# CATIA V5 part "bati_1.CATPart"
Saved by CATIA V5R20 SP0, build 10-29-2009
Part number: sqlt_bati_1
Publications: "Plan.1", "Point.1", "Point.2", "Droite.1", "Droite.2", "Point.3", "Point.4", "Point.5", "Point.6", "Point.7", "Point.8", "Point.9", "Droite.3", "Point.10", "Point.11", "Point.12", "Point.13", "Point.14", "Point.15", "Point.16", "Point.17", "Plan.2", "Plan.3", "Plan.4", "Point.18", "Plan.5", "écartement_pivot_bati", "largueur_rail_coulisseau", "longueur_rail_coulisseau", "Plan.6", "Droite.4"
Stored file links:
  D:\ecole\thinkmotion\IAO\bati_1.CATPart
  D:\ecole\thinkmotion\IAO\sqlt mecanisme coulisseau.CATProduct
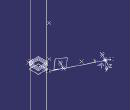
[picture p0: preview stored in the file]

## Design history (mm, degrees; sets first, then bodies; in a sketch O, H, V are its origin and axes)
Parameters
  `écartement_pivot_bati` = 100 mm {= `External.écartement_pivots`}
  largueur_rail_coulisseau = 50 mm {= External.largueur_rail_coulisseau}
  longueur_rail_coulisseau = 200 mm {= External.longueur_rail_coulisseau}
External parameters (linked from other documents)
  External.rayon_pivot_bati = 10 mm
  `External.épaisseur_piece` = 20 mm
  `External.écartement_pivots` = 100 mm
  External.largueur_rail_coulisseau = 50 mm
  External.longueur_rail_coulisseau = 200 mm
AxisSystem1: origin (-243.1672, 186.5836, 0), X (0.8944, -0.4472, 0), Y (0, 0, -1), Z (0.4472, 0.8944, 0)
Set1 "sqlt_bati"
  Plane1: type Offset, RefPlane xy-plane, Offset 0
  Point1: (0, 50 {= `écartement_pivot_bati` /2}, 0)
  Point2: (0, -50 {= -`écartement_pivot_bati` /2}, 0)
  Line1: type PtDir, RefPoint Point1, Direction Plane1, Start 0, End 20
  Line2: type PtDir, RefPoint Point2, Direction Plane1, Start 0, End 20
  Point3: (0, 40 {= `écartement_pivot_bati` /2-External.rayon_pivot_bati}, 0)
  Point4: (0, -40 {= -`écartement_pivot_bati` /2+External.rayon_pivot_bati}, 0)
  Point5: (0, 65 {= `écartement_pivot_bati` /2+External.rayon_pivot_bati +5mm}, 0)
  Point6: (15 {= External.rayon_pivot_bati +5mm}, -50 {= -`écartement_pivot_bati` /2}, 0)
  Point7: (-70, 0, 0)
  Point8: (-200 {= -100mm-longueur_rail_coulisseau /2}, 200 {= `écartement_pivot_bati` +`écartement_pivot_bati` /2+largueur_rail_coulisseau}, 0), relative to Point7
  Point9: (-200 {= -100mm-longueur_rail_coulisseau /2}, -200 {= -`écartement_pivot_bati` -`écartement_pivot_bati` /2-largueur_rail_coulisseau}, 0), relative to Point7
  Line3: type PtPt, FirstPoint Point5, SecondPoint Point8
  Point10: type OnCurve, Support Line3, Length 30
  Point11: (0, 0, -50 {= -largueur_rail_coulisseau}), relative to Point10, in AxisSystem1
  Point12: (200 {= longueur_rail_coulisseau}, 0, -50 {= -largueur_rail_coulisseau}), in AxisSystem1
  Point13: (200 {= longueur_rail_coulisseau}, 0, 0), relative to Point10, in AxisSystem1
  Point14: (0, 0, -10), relative to Point10, in AxisSystem1
  Point15: (0, 0, -40 {= -largueur_rail_coulisseau +10mm}), in AxisSystem1
  Point16: (200 {= longueur_rail_coulisseau}, 0, -40 {= -largueur_rail_coulisseau +10mm}), in AxisSystem1
  Point17: (200 {= longueur_rail_coulisseau}, 0, -10), in AxisSystem1
  Plane2: type Offset, RefPlane Plane1, Offset 20 {= `External.épaisseur_piece`}
  Plane3: type Offset, RefPlane xy-plane, Offset 6.6667 {= 1/3*`External.épaisseur_piece`}
  Plane4: type Offset, RefPlane xy-plane, Offset 13.3333 {= 2/3*`External.épaisseur_piece`}
  Point18: (100 {= longueur_rail_coulisseau /2}, 10, -40 {= -largueur_rail_coulisseau  +10mm}), relative to Point10, in AxisSystem1
  Plane5: type 3Points, Element1 Point16, Element2 Point18, Element3 Point15
  Plane6: type Offset, RefPlane Plane1, Offset 20 {= `External.épaisseur_piece`}, reversed
Body1 (main body)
